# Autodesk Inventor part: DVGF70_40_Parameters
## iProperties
Created: 2010-04
Part Number: DVGF70_40_Parameters
Document SubType Name: Modeling
Designer: TB
Density: 1 g/cm^3
Slaglengde: 100.000 mm
Vinkel_Plussport: 0.00 deg
Vinkel_Minusport: 0.00 deg
Forlengelse_rør: 0.000 mm
Author: TB
